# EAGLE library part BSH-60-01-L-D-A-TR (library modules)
iMX31 MODULE connector Samtec BSH-D connector 120-pins Same as on iMX31-CPU module
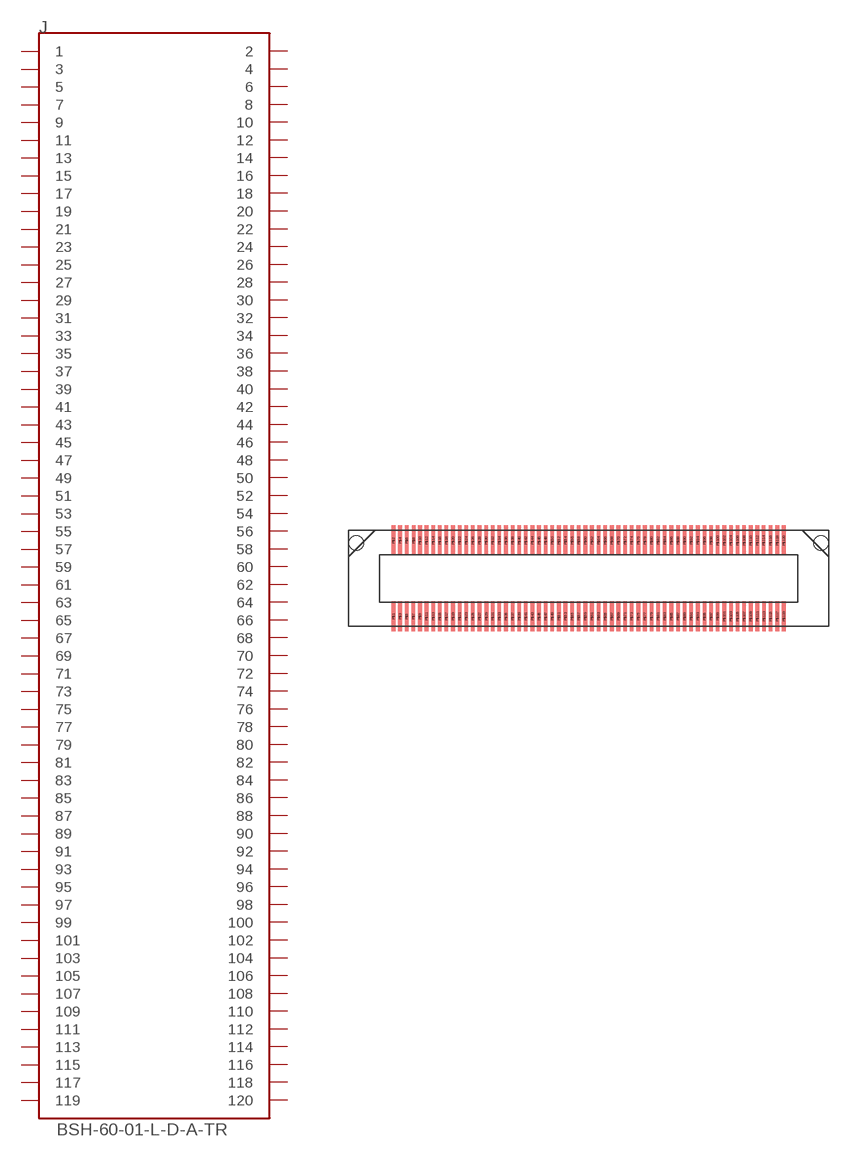
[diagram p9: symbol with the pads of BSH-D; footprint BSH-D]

Designator prefix J

## BSH-60-01-L-D-A-TR  [BSH-D]
P$1  1
P$2  2
P$3  3
P$4  4
P$5  5
P$6  6
P$7  7
P$8  8
P$9  9
P$10  10
P$11  11
P$12  12
P$13  13
P$14  14
P$15  15
P$16  16
P$17  17
P$18  18
P$19  19
P$20  20
P$21  21
P$22  22
P$23  23
P$24  24
P$25  25
P$26  26
P$27  27
P$28  28
P$29  29
P$30  30
P$31  31
P$32  32
P$33  33
P$34  34
P$35  35
P$36  36
P$37  37
P$38  38
P$39  39
P$40  40
P$41  41
P$42  42
P$43  43
P$44  44
P$45  45
P$46  46
P$47  47
P$48  48
P$49  49
P$50  50
P$51  51
P$52  52
P$53  53
P$54  54
P$55  55
P$56  56
P$57  57
P$58  58
P$59  59
P$60  60
P$61  61
P$62  62
P$63  63
P$64  64
P$65  65
P$66  66
P$67  67
P$68  68
P$69  69
P$70  70
P$71  71
P$72  72
P$73  73
P$74  74
P$75  75
P$76  76
P$77  77
P$78  78
P$79  79
P$80  80
P$81  81
P$82  82
P$83  83
P$84  84
P$85  85
P$86  86
P$87  87
P$88  88
P$89  89
P$90  90
P$91  91
P$92  92
P$93  93
P$94  94
P$95  95
P$96  96
P$97  97
P$98  98
P$99  99
P$100  100
P$101  101
P$102  102
P$103  103
P$104  104
P$105  105
P$106  106
P$107  107
P$108  108
P$109  109
P$110  110
P$111  111
P$112  112
P$113  113
P$114  114
P$115  115
P$116  116
P$117  117
P$118  118
P$119  119
P$120  120

## Footprint BSH-D (pad centres in mm)
smd 0.279 x 2.273: P$1 -14.75,-2.864; P$2 -14.75,2.864; P$3 -14.25,-2.864; P$4 -14.25,2.864; P$5 -13.75,-2.864; P$6 -13.75,2.864; P$7 -13.25,-2.864; P$8 -13.225,2.864; P$9 -12.75,-2.864; P$10 -12.75,2.864; P$11 -12.25,-2.864; P$12 -12.25,2.864; P$13 -11.75,-2.864; P$14 -11.75,2.864; P$15 -11.25,-2.864; P$16 -11.25,2.864; P$17 -10.75,-2.864; P$18 -10.75,2.864; P$19 -10.25,-2.864; P$20 -10.25,2.864; P$21 -9.75,-2.864; P$22 -9.75,2.864; P$23 -9.25,-2.864; P$24 -9.25,2.864; P$25 -8.75,-2.864; P$26 -8.75,2.864; P$27 -8.25,-2.864; P$28 -8.25,2.864; P$29 -7.725,-2.864; P$30 -7.75,2.864; P$31 -7.25,-2.864; P$32 -7.25,2.864; P$33 -6.75,-2.864; P$34 -6.75,2.864; P$35 -6.25,-2.864; P$36 -6.25,2.864; P$37 -5.75,-2.864; P$38 -5.75,2.864; P$39 -5.25,-2.864; P$40 -5.25,2.864; P$41 -4.75,-2.864; P$42 -4.75,2.864; P$43 -4.25,-2.864; P$44 -4.25,2.864; P$45 -3.75,-2.864; P$46 -3.75,2.864; P$47 -3.25,-2.864; P$48 -3.25,2.864; P$49 -2.75,-2.864; P$50 -2.75,2.864; P$51 -2.25,-2.864; P$52 -2.25,2.864; P$53 -1.75,-2.864; P$54 -1.75,2.864; P$55 -1.25,-2.864; P$56 -1.25,2.864; P$57 -0.75,-2.864; P$58 -0.75,2.864; P$59 -0.25,-2.864; P$60 -0.25,2.864; P$61 0.25,-2.864; P$62 0.25,2.864; P$63 0.75,-2.864; P$64 0.75,2.864; P$65 1.25,-2.864; P$66 1.25,2.864; P$67 1.75,-2.864; P$68 1.75,2.864; P$69 2.25,-2.864; P$70 2.25,2.864; P$71 2.75,-2.864; P$72 2.75,2.864; P$73 3.25,-2.864; P$74 3.25,2.864; P$75 3.75,-2.864; P$76 3.75,2.864; P$77 4.25,-2.864; P$78 4.25,2.864; P$79 4.75,-2.864; P$80 4.75,2.864; P$81 5.25,-2.864; P$82 5.25,2.864; P$83 5.75,-2.864; P$84 5.75,2.864; P$85 6.25,-2.864; P$86 6.25,2.864; P$87 6.75,-2.864; P$88 6.75,2.864; P$89 7.25,-2.864; P$90 7.25,2.864; P$91 7.75,-2.864; P$92 7.75,2.864; P$93 8.25,-2.864; P$94 8.25,2.864; P$95 8.75,-2.864; P$96 8.75,2.864; P$97 9.25,-2.864; P$98 9.25,2.864; P$99 9.75,-2.864; P$100 9.75,2.864; P$101 10.25,-2.864; P$102 10.25,2.864; P$103 10.75,-2.864; P$104 10.75,2.864; P$105 11.25,-2.864; P$106 11.25,2.864; P$107 11.75,-2.864; P$108 11.75,2.864; P$109 12.25,-2.864; P$110 12.25,2.864; P$111 12.75,-2.864; P$112 12.75,2.864; P$113 13.25,-2.864; P$114 13.225,2.864; P$115 13.75,-2.864; P$116 13.75,2.864; P$117 14.25,-2.864; P$118 14.25,2.864; P$119 14.75,-2.864; P$120 14.75,2.864
hole 1.1 at -17.563,2.666
hole 1.1 at 17.563,2.666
